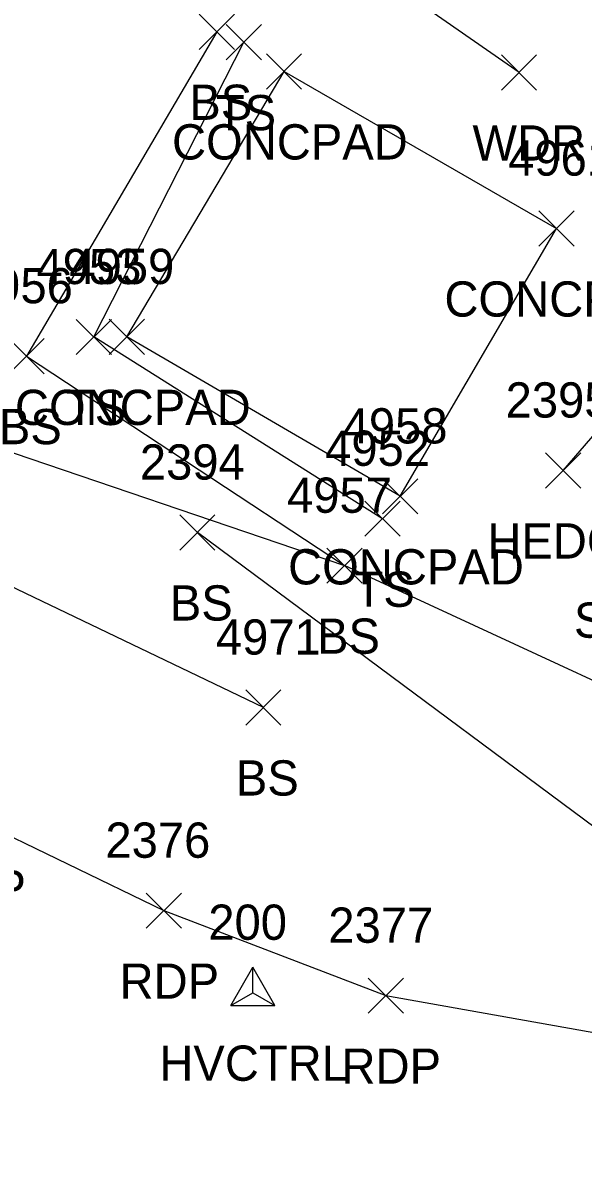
# Model space of a CAD drawing. Extents: x 1653135 to 1655489, y 602711 to 605684.
# Drawn here: x 1653657.5 to 1653689.3, y 605260.3 to 605324.9 of the extents above; entities that cross this region are included whole.
import ezdxf

# ---------------------------------------------------------------- set-up
doc = ezdxf.new("R2010")
doc.units = 0
for name, color, linetype in [('C_A', 7, 'Continuous'), ('C_I', 7, 'Continuous'), ('CPSM', 7, 'Continuous'), ('L_A', 7, 'Continuous'), ('L_I', 7, 'Continuous'), ('L_TIC', 7, 'Continuous'), ('LAHR', 7, 'Continuous'), ('LAWA', 7, 'Continuous'), ('LELB', 7, 'Continuous'), ('LS', 7, 'Continuous'), ('P_A', 7, 'Continuous'), ('P_I', 7, 'Continuous'), ('P_TIC', 7, 'Continuous'), ('PET', 7, 'Continuous'), ('R_A', 7, 'Continuous'), ('RDG', 7, 'Continuous')]:
    doc.layers.add(name, color=color, linetype=linetype)

msp = doc.modelspace()

# ---------------------------------------------------------------- linework, layer by layer
at = {"layer": 'CPSM'}
for p, q in [((1653669.28, 605269.1), (1653670.53, 605271.265)), ((1653671.78, 605269.1), (1653670.53, 605271.265)), ((1653670.53, 605269.821), (1653670.53, 605271.265)), ((1653669.28, 605269.1), (1653670.53, 605269.821)), ((1653670.53, 605269.821), (1653670.53, 605269.821)), ((1653670.53, 605269.821), (1653671.78, 605269.1)), ((1653669.28, 605269.1), (1653671.78, 605269.1))]:
    msp.add_line(p, q, dxfattribs=at)
at = {"layer": 'L_TIC'}
for points in [[(1653667.484, 605323.351), (1653669.484, 605325.351)], [(1653669.484, 605323.351), (1653667.484, 605325.351)], [(1653667.484, 605323.351), (1653669.484, 605325.351)], [(1653669.484, 605323.351), (1653667.484, 605325.351)], [(1653669.021, 605322.763), (1653671.021, 605324.763)], [(1653671.021, 605322.763), (1653669.021, 605324.763)], [(1653669.021, 605322.763), (1653671.021, 605324.763)], [(1653671.021, 605322.763), (1653669.021, 605324.763)], [(1653671.297, 605321.103), (1653673.297, 605323.103)], [(1653673.297, 605321.103), (1653671.297, 605323.103)], [(1653671.297, 605321.103), (1653673.297, 605323.103)], [(1653673.297, 605321.103), (1653671.297, 605323.103)], [(1653684.625, 605321.041), (1653686.625, 605323.041)], [(1653686.625, 605321.041), (1653684.625, 605323.041)], [(1653684.625, 605321.041), (1653686.625, 605323.041)], [(1653686.625, 605321.041), (1653684.625, 605323.041)], [(1653686.749, 605312.187), (1653688.749, 605314.187)], [(1653688.749, 605312.187), (1653686.749, 605314.187)], [(1653686.749, 605312.187), (1653688.749, 605314.187)], [(1653688.749, 605312.187), (1653686.749, 605314.187)], [(1653686.749, 605312.187), (1653688.749, 605314.187)], [(1653688.749, 605312.187), (1653686.749, 605314.187)], [(1653686.749, 605312.187), (1653688.749, 605314.187)], [(1653688.749, 605312.187), (1653686.749, 605314.187)], [(1653660.515, 605306.033), (1653662.515, 605308.033)], [(1653662.515, 605306.033), (1653660.515, 605308.033)], [(1653660.515, 605306.033), (1653662.515, 605308.033)], [(1653662.515, 605306.033), (1653660.515, 605308.033)], [(1653662.388, 605306.036), (1653664.388, 605308.036)], [(1653664.388, 605306.036), (1653662.388, 605308.036)], [(1653662.388, 605306.036), (1653664.388, 605308.036)], [(1653664.388, 605306.036), (1653662.388, 605308.036)], [(1653656.684, 605304.945), (1653658.684, 605306.945)], [(1653658.684, 605304.945), (1653656.684, 605306.945)], [(1653656.684, 605304.945), (1653658.684, 605306.945)], [(1653658.684, 605304.945), (1653656.684, 605306.945)], [(1653687.126, 605298.458), (1653689.126, 605300.458)], [(1653689.126, 605298.458), (1653687.126, 605300.458)], [(1653687.126, 605298.458), (1653689.126, 605300.458)], [(1653689.126, 605298.458), (1653687.126, 605300.458)], [(1653677.882, 605296.989), (1653679.882, 605298.989)], [(1653679.882, 605296.989), (1653677.882, 605298.989)], [(1653677.882, 605296.989), (1653679.882, 605298.989)], [(1653679.882, 605296.989), (1653677.882, 605298.989)], [(1653677.882, 605296.989), (1653679.882, 605298.989)], [(1653679.882, 605296.989), (1653677.882, 605298.989)], [(1653677.882, 605296.989), (1653679.882, 605298.989)], [(1653679.882, 605296.989), (1653677.882, 605298.989)], [(1653676.886, 605295.719), (1653678.886, 605297.719)], [(1653678.886, 605295.719), (1653676.886, 605297.719)], [(1653676.886, 605295.719), (1653678.886, 605297.719)], [(1653678.886, 605295.719), (1653676.886, 605297.719)], [(1653666.38, 605294.938), (1653668.38, 605296.938)], [(1653668.38, 605294.938), (1653666.38, 605296.938)], [(1653666.38, 605294.938), (1653668.38, 605296.938)], [(1653668.38, 605294.938), (1653666.38, 605296.938)], [(1653674.729, 605293.055), (1653676.729, 605295.055)], [(1653676.729, 605293.055), (1653674.729, 605295.055)], [(1653674.729, 605293.055), (1653676.729, 605295.055)], [(1653676.729, 605293.055), (1653674.729, 605295.055)], [(1653670.125, 605285.007), (1653672.125, 605287.007)], [(1653672.125, 605285.007), (1653670.125, 605287.007)], [(1653670.125, 605285.007), (1653672.125, 605287.007)], [(1653672.125, 605285.007), (1653670.125, 605287.007)]]:
    msp.add_lwpolyline(points, dxfattribs=at)
at = {"layer": 'LAHR'}
msp.add_lwpolyline([(1653688.126, 605299.458), (1653695.956, 605308.517)], dxfattribs=at)
at = {"layer": 'LAWA'}
msp.add_lwpolyline([(1653685.625, 605322.041), (1653670.875, 605332.317), (1653661.715, 605337.52), (1653630.344, 605321.685), (1653616.8, 605320.721), (1653598.434, 605325.947), (1653564.063, 605344.005), (1653534.847, 605363.007), (1653505.816, 605383.054), (1653484.897, 605402.837), (1653463.33, 605422.395), (1653441.693, 605442.638), (1653418.025, 605465.086), (1653400.643, 605492.124), (1653388.1, 605504.014)], dxfattribs=at)
at = {"layer": 'LELB'}
for points in [[(1653668.484, 605324.351), (1653657.684, 605305.945), (1653675.729, 605294.055)], [(1653677.886, 605296.719), (1653661.515, 605307.033), (1653670.021, 605323.763)], [(1653714.941, 605267.501), (1653697.737, 605273.383), (1653667.38, 605295.938)], [(1653671.125, 605286.007), (1653654.356, 605294.046), (1653639.293, 605295.296)]]:
    msp.add_lwpolyline(points, dxfattribs=at)
at = {"layer": 'LS'}
for points in [[(1653678.882, 605297.989), (1653663.388, 605307.036), (1653672.297, 605322.103), (1653687.749, 605313.187)], [(1653678.882, 605297.989), (1653687.749, 605313.187)]]:
    msp.add_lwpolyline(points, dxfattribs=at)
at = {"layer": 'P_TIC'}
for points in [[(1653664.481, 605273.477), (1653666.481, 605275.477)], [(1653666.481, 605273.477), (1653664.481, 605275.477)], [(1653664.481, 605273.477), (1653666.481, 605275.477)], [(1653666.481, 605273.477), (1653664.481, 605275.477)], [(1653677.068, 605268.653), (1653679.068, 605270.653)], [(1653679.068, 605268.653), (1653677.068, 605270.653)], [(1653677.068, 605268.653), (1653679.068, 605270.653)], [(1653679.068, 605268.653), (1653677.068, 605270.653)]]:
    msp.add_lwpolyline(points, dxfattribs=at)
at = {"layer": 'PET'}
msp.add_lwpolyline([(1653654.524, 605279.776), (1653665.481, 605274.477), (1653678.068, 605269.653), (1653696.029, 605266.473), (1653709.03, 605265.366), (1653717.526, 605266.073), (1653726.648, 605268.269), (1653743.088, 605277.115), (1653755.463, 605259.253), (1653765.921, 605244.563), (1653757.558, 605236.881), (1653747.498, 605222.75), (1653729.711, 605207.167), (1653718.29, 605197.382), (1653709.642, 605189.343), (1653699.377, 605174.783), (1653695.369, 605174.396), (1653690.143, 605165.647), (1653683.772, 605149.176), (1653674.351, 605119.826), (1653662.023, 605081.754)], dxfattribs=at)
at = {"layer": 'RDG'}
for points in [[(1653654.135, 605301.398), (1653675.729, 605294.055)], [(1653702.376, 605281.724), (1653675.729, 605294.055)]]:
    msp.add_lwpolyline(points, dxfattribs=at)

# ---------------------------------------------------------------- texts
at = {"layer": 'C_A'}
msp.add_text('HVCTRL', height=2, dxfattribs=at).set_placement((1653665.223, 605264.821))
at = {"layer": 'C_I'}
msp.add_text('200', height=2, dxfattribs=at).set_placement((1653668.003, 605272.821))
at = {"layer": 'L_A'}
for s, p in [('BS', (1653666.925, 605319.351)), ('BS', (1653666.925, 605319.351)), ('TS', (1653668.43, 605318.763)), ('TS', (1653668.43, 605318.763)), ('CONCPAD', (1653665.943, 605317.103)), ('CONCPAD', (1653665.943, 605317.103)), ('WDR', (1653682.987, 605317.041)), ('WDR', (1653682.987, 605317.041)), ('CONCPAD', (1653681.395, 605308.187)), ('CONCPAD', (1653681.395, 605308.187)), ('CONCPAD', (1653681.395, 605308.187)), ('CONCPAD', (1653681.395, 605308.187)), ('CONCPAD', (1653657.034, 605302.036)), ('CONCPAD', (1653657.034, 605302.036)), ('TS', (1653659.925, 605302.033)), ('TS', (1653659.925, 605302.033)), ('BS', (1653656.125, 605300.945)), ('BS', (1653656.125, 605300.945)), ('HEDGE', (1653683.827, 605294.458)), ('HEDGE', (1653683.827, 605294.458)), ('CONCPAD', (1653672.527, 605292.989)), ('CONCPAD', (1653672.527, 605292.989)), ('CONCPAD', (1653672.527, 605292.989)), ('CONCPAD', (1653672.527, 605292.989)), ('TS', (1653676.296, 605291.719)), ('TS', (1653676.296, 605291.719)), ('BS', (1653665.821, 605290.938)), ('BS', (1653665.821, 605290.938)), ('BS', (1653674.17, 605289.055)), ('BS', (1653674.17, 605289.055)), ('BS', (1653669.566, 605281.007)), ('BS', (1653669.566, 605281.007))]:
    msp.add_text(s, height=2, dxfattribs=at).set_placement(p)
at = {"layer": 'L_I'}
for s, p in [('4961', (1653685.009, 605316.187)), ('4961', (1653685.009, 605316.187)), ('4961', (1653685.009, 605316.187)), ('4961', (1653685.009, 605316.187)), ('4953', (1653658.256, 605310.033)), ('4953', (1653658.256, 605310.033)), ('4959', (1653660.12, 605310.036)), ('4959', (1653660.12, 605310.036)), ('4956', (1653654.37, 605308.945)), ('4956', (1653654.37, 605308.945)), ('2395', (1653684.866, 605302.458)), ('2395', (1653684.866, 605302.458)), ('4958', (1653675.622, 605300.989)), ('4958', (1653675.622, 605300.989)), ('4958', (1653675.622, 605300.989)), ('4958', (1653675.622, 605300.989)), ('4952', (1653674.627, 605299.719)), ('4952', (1653674.627, 605299.719)), ('2394', (1653664.12, 605298.938)), ('2394', (1653664.12, 605298.938)), ('4957', (1653672.469, 605297.055)), ('4957', (1653672.469, 605297.055)), ('4971', (1653668.432, 605289.007)), ('4971', (1653668.432, 605289.007))]:
    msp.add_text(s, height=2, dxfattribs=at).set_placement(p)
at = {"layer": 'P_A'}
for p in [(1653652.012, 605274.776), (1653652.012, 605274.776), (1653662.969, 605269.477), (1653662.969, 605269.477), (1653675.556, 605264.653), (1653675.556, 605264.653)]:
    msp.add_text('RDP', height=2, dxfattribs=at).set_placement(p)
at = {"layer": 'P_I'}
for s, p in [('2376', (1653662.166, 605277.477)), ('2376', (1653662.166, 605277.477)), ('2377', (1653674.809, 605272.653)), ('2377', (1653674.809, 605272.653))]:
    msp.add_text(s, height=2, dxfattribs=at).set_placement(p)
at = {"layer": 'R_A'}
msp.add_text('SHED SWC ST', height=2, dxfattribs=at).set_placement((1653688.743, 605289.964))
msp.add_text('SHED SWC ST', height=2, dxfattribs=at).set_placement((1653688.743, 605289.964))

doc.saveas('drawing.dxf')
